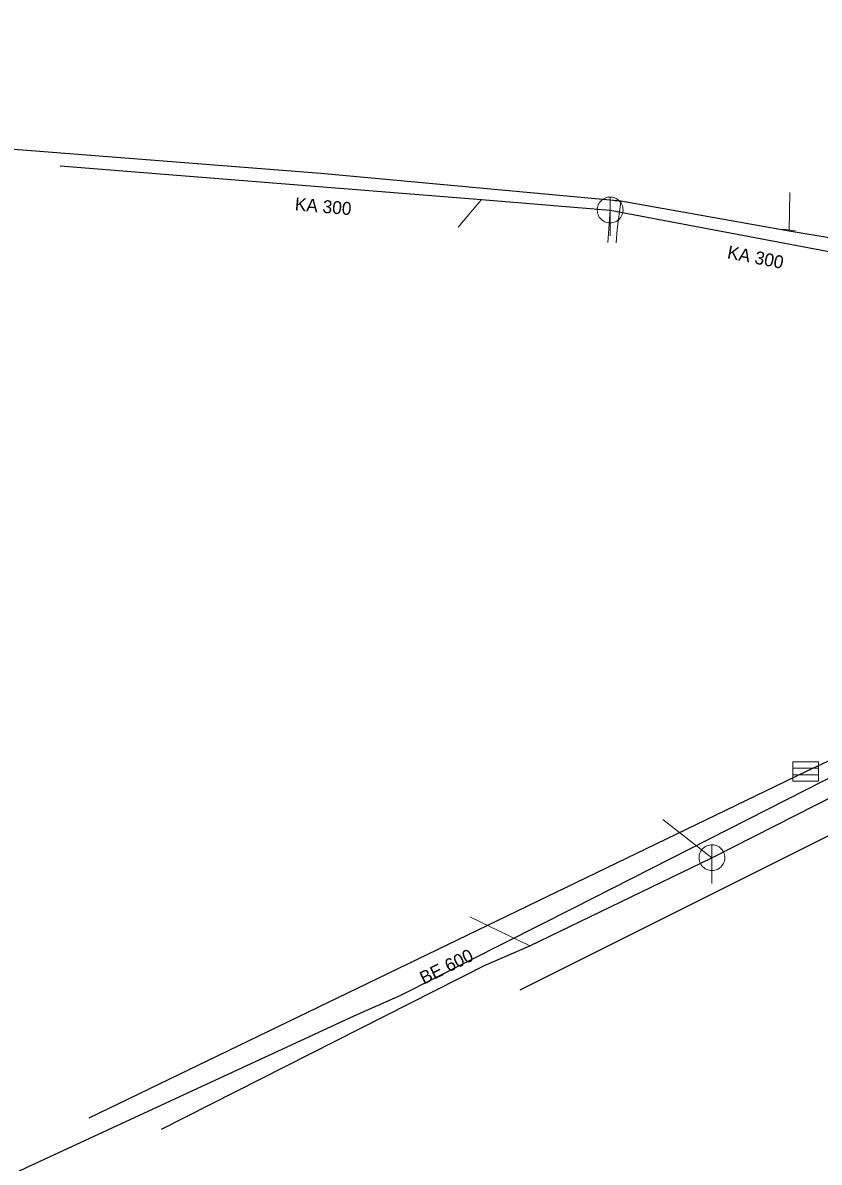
# Model space of a CAD drawing. Extents: x -690535 to -689974, y -975624 to -975325.
# Drawn here: x -690430.6 to -690368.9, y -975523.3 to -975435 of the extents above; entities that cross this region are included whole.
import ezdxf

# ---------------------------------------------------------------- set-up
doc = ezdxf.new("R2010")
doc.units = 0
doc.header["$LTSCALE"] = 0.4
for name, color, linetype, lineweight in [('1', 7, 'Continuous', 13), ('11', 7, 'Continuous', 13), ('13', 7, 'Continuous', 13), ('14', 7, 'Continuous', 25), ('17', 7, 'Continuous', 25), ('22', 7, 'Continuous', 13), ('34', 7, 'Continuous', 13)]:
    doc.layers.add(name, color=color, linetype=linetype, lineweight=lineweight)

msp = doc.modelspace()

# ---------------------------------------------------------------- linework, layer by layer
at = {"layer": '11'}
for p, q in [((-690396.829, -975450.833), (-690395.028, -975448.712)), ((-690385.245, -975452.021), (-690385.074, -975449.513)), ((-690380.98, -975496.73), (-690377.19, -975499.69)), ((-690395.93, -975504.26), (-690391.289, -975506.52))]:
    msp.add_line(p, q, dxfattribs=at)
at = {"layer": '13'}
msp.add_line((-690371.213, -975451.069), (-690371.168, -975448.147), dxfattribs=at)
msp.add_lwpolyline([(-690384.238, -975448.845), (-690384.515, -975451.011), (-690384.592, -975452.05)], dxfattribs=at)
at = {"layer": '14', "lineweight": 13}
for p, q in [((-690384.232, -975448.792), (-690384.238, -975448.845)), ((-690371.219, -975451.123), (-690371.213, -975451.069))]:
    msp.add_line(p, q, dxfattribs=at)
at = {"layer": '14'}
for p, q in [((-690385.074, -975449.513), (-690360.401, -975454.191)), ((-690369.923, -975493.022), (-690316.232, -975467.417)), ((-690392.036, -975509.912), (-690333.67, -975480.756)), ((-690425.419, -975519.844), (-690369.923, -975493.022))]:
    msp.add_line(p, q, dxfattribs=at)
for points in [[(-690427.668, -975446.087), (-690395.028, -975448.712), (-690385.074, -975449.513)], [(-690419.82, -975520.71), (-690394.789, -975508.03), (-690391.289, -975506.52), (-690377.19, -975499.69), (-690356.199, -975489.039), (-690332.539, -975477.879), (-690325.927, -975474.555)]]:
    msp.add_lwpolyline(points, dxfattribs=at)
at = {"layer": '17'}
for points in [[(-690535.418, -975444.785), (-690534.453, -975442.263), (-690513.173, -975435.01), (-690489.543, -975438.213), (-690462.828, -975441.78), (-690461.125, -975442.127), (-690435.879, -975444.436), (-690407.486, -975446.66), (-690384.232, -975448.792), (-690371.219, -975451.123), (-690363.91, -975452.34), (-690340.249, -975460.384), (-690334.125, -975470.528)], [(-690487.124, -975551.552), (-690473.512, -975544.629), (-690473.092, -975544.418), (-690468.651, -975542.14), (-690430.232, -975523.675), (-690404.89, -975511.94), (-690401.289, -975510.34), (-690387.871, -975503.577), (-690350.486, -975484.551), (-690338.608, -975478.999)]]:
    msp.add_lwpolyline(points, dxfattribs=at)
at = {"layer": '22'}
for p, q in [((-690385.074, -975451.513), (-690385.073, -975448.513)), ((-690370.934, -975492.765), (-690368.934, -975492.765)), ((-690370.934, -975493.265), (-690368.934, -975493.265)), ((-690377.19, -975501.69), (-690377.189, -975498.69))]:
    msp.add_line(p, q, dxfattribs=at)
for points in [[(-690384.074, -975449.513), (-690384.079, -975449.404), (-690384.097, -975449.296), (-690384.127, -975449.19), (-690384.167, -975449.089), (-690384.219, -975448.992), (-690384.281, -975448.902), (-690384.353, -975448.819), (-690384.433, -975448.745), (-690384.521, -975448.679), (-690384.615, -975448.624), (-690384.715, -975448.579), (-690384.82, -975448.546), (-690384.927, -975448.524), (-690385.036, -975448.514), (-690385.146, -975448.516), (-690385.254, -975448.53), (-690385.361, -975448.555), (-690385.464, -975448.592), (-690385.562, -975448.641), (-690385.654, -975448.699), (-690385.74, -975448.768), (-690385.817, -975448.845), (-690385.886, -975448.931), (-690385.945, -975449.023), (-690385.993, -975449.121), (-690386.03, -975449.224), (-690386.056, -975449.331), (-690386.07, -975449.439), (-690386.073, -975449.549), (-690386.063, -975449.658), (-690386.042, -975449.765), (-690386.008, -975449.869), (-690385.964, -975449.969), (-690385.909, -975450.064), (-690385.843, -975450.152), (-690385.769, -975450.232), (-690385.686, -975450.304), (-690385.596, -975450.366), (-690385.5, -975450.418), (-690385.398, -975450.459), (-690385.293, -975450.489), (-690385.185, -975450.507), (-690385.075, -975450.513), (-690384.966, -975450.507), (-690384.858, -975450.489), (-690384.753, -975450.46), (-690384.651, -975450.419), (-690384.554, -975450.367), (-690384.464, -975450.305), (-690384.381, -975450.234), (-690384.306, -975450.154), (-690384.241, -975450.066), (-690384.185, -975449.972), (-690384.141, -975449.872), (-690384.107, -975449.768), (-690384.085, -975449.66), (-690384.075, -975449.551)], [(-690370.934, -975492.265), (-690368.934, -975492.265), (-690368.934, -975493.765), (-690370.934, -975493.765)], [(-690376.19, -975499.69), (-690376.195, -975499.581), (-690376.213, -975499.473), (-690376.243, -975499.367), (-690376.283, -975499.266), (-690376.335, -975499.169), (-690376.397, -975499.079), (-690376.469, -975498.996), (-690376.549, -975498.922), (-690376.637, -975498.856), (-690376.731, -975498.801), (-690376.831, -975498.756), (-690376.936, -975498.723), (-690377.043, -975498.701), (-690377.152, -975498.691), (-690377.262, -975498.693), (-690377.37, -975498.707), (-690377.477, -975498.732), (-690377.58, -975498.769), (-690377.678, -975498.818), (-690377.77, -975498.876), (-690377.856, -975498.945), (-690377.933, -975499.022), (-690378.002, -975499.108), (-690378.061, -975499.2), (-690378.109, -975499.298), (-690378.146, -975499.401), (-690378.172, -975499.508), (-690378.186, -975499.616), (-690378.189, -975499.726), (-690378.179, -975499.835), (-690378.158, -975499.942), (-690378.124, -975500.046), (-690378.08, -975500.146), (-690378.025, -975500.241), (-690377.959, -975500.329), (-690377.885, -975500.409), (-690377.802, -975500.481), (-690377.712, -975500.543), (-690377.616, -975500.595), (-690377.514, -975500.636), (-690377.409, -975500.666), (-690377.301, -975500.684), (-690377.191, -975500.69), (-690377.082, -975500.684), (-690376.974, -975500.666), (-690376.869, -975500.637), (-690376.767, -975500.596), (-690376.67, -975500.544), (-690376.58, -975500.482), (-690376.497, -975500.411), (-690376.422, -975500.331), (-690376.357, -975500.243), (-690376.301, -975500.149), (-690376.257, -975500.049), (-690376.223, -975499.945), (-690376.201, -975499.837), (-690376.191, -975499.728)]]:
    msp.add_lwpolyline(points, close=True, dxfattribs=at)
at = {"layer": '34'}
for p, q in [((-690383.74, -975448.893), (-690384.735, -975448.795)), ((-690371.708, -975451.005), (-690370.717, -975451.133))]:
    msp.add_line(p, q, dxfattribs=at)

# ---------------------------------------------------------------- texts
at = {"layer": '1'}
for s, rotation, p in [('KA 300', 355, (-690409.52, -975449.537)), ('KA 300', 349, (-690376.055, -975453.243)), ('BE 600', 26, (-690399.508, -975509.526))]:
    msp.add_text(s, height=1, rotation=rotation, dxfattribs=at).set_placement(p)

doc.saveas('drawing.dxf')
